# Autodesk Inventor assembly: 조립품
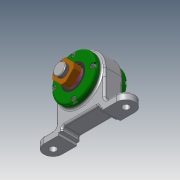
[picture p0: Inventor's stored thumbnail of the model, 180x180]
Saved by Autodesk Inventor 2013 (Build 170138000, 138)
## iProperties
Created: 2019-05
Part Number: 조립품
Document SubType Name: Assembly
Designer: 00
Author: 00
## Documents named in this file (13)
- C:\Users\00\Desktop\490504V1021\조립품.iam
- C:\Users\00\Desktop\490504V1021\본체.ipt
- C:\Users\00\Desktop\490504V1021\개스킷.ipt
- C:\Users\00\Desktop\490504V1021\그리스니플 M6.ipt
- 그리스니플  M6.ipt
- C:\Users\00\Desktop\490504V1021\그리스니플개스킷.ipt
- C:\Users\00\Desktop\490504V1021\베어링너트.ipt
- C:\Users\00\Desktop\490504V1021\볼트 M4.ipt
- C:\Users\00\Desktop\490504V1021\앵귤러 볼 베어링 7205.ipt
- C:\Users\00\Desktop\490504V1021\오일 실 28 40 5 B.ipt
- C:\Users\00\Desktop\490504V1021\축.ipt
- C:\Users\00\Desktop\490504V1021\칼라.ipt
- C:\Users\00\Desktop\490504V1021\커버.ipt
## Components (4 placed, 3 different names)
1. 개스킷:1
2. 그리스니플  M6:1 — 각도:1, 각도:2
3. 그리스니플개스킷:1
4. 개스킷:2
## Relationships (2: Angle 2)
- 각도:1 [Angle]: 그리스니플  M6:1
- 각도:2 [Angle]: 그리스니플  M6:1
